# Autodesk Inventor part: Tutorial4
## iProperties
Shininess: 64.0
Length Units: 11269
Angle Units: 11279
Time Units: 11290
Mass Units: 11283
Length Display Precision: 3
Angle Display Precision: 2
Compacted: True
Part Number: Tutorial4
Document SubType Name: Modeling
Created: 2002-12
Designer: deepak
Density: 0.0
Volumn: 0.0
Area: 0.0
PropertySet Name: Model Information
Control State: 0
Master: False
Checked Out: False
Author: deepak
